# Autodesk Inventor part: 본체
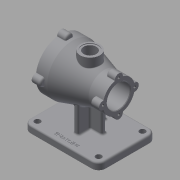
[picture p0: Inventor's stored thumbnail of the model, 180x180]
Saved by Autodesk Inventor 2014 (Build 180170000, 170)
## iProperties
Created: 2020-12
Part Number: 본체
Material: Generic
Document SubType Name: Modeling
Designer: kh
Density: 1 g/cm^3
Appearance: Default
Author: kh
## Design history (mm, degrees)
sketch "스케치1"
  geometry: L1 (-65, -50)-(65, -50); L2 (65, -50)-(65, 50); L3 (65, 50)-(-65, 50); L4 (-65, 50)-(-65, -50); L5 (-65, -50)-(65, 50); L6 (65, -50)-(-65, 50); 1 further point
  constraints: 12 end point, 2 midpoint, 2 parallel, 1 horizontal, 1 perpendicular
  dimensions: "d0" = 130 distance of L1.start L1.end; "d1" = 100 distance of L1.end L2.end
extrude "돌출1" new body sketch "스케치1" distance "d2" = 12; taper "d3" = 0 deg
fillet "모깎기1" dims "d4" = 12
sketch "스케치2"
  geometry: 1 further point
sketch "스케치3"
  geometry: 1 further point
sketch "스케치4"
  geometry: L1 (-65, 38)-(-65, -38) reference; L2 (-53, -50)-(53, -50) reference; L3 (65, -38)-(65, 38) reference; L4 (53, 50)-(-53, 50) reference; C1 r 5 at (-53, 38); C2 r 5 at (53, 38); C3 r 5 at (53, -38); C4 r 5 at (-53, -38); A1 r 12 centre (-53, 38) between (-53, 50) and (-65, 38) reference; A2 r 12 centre (-53, -38) between (-65, -38) and (-53, -50) reference; A3 r 12 centre (53, -38) between (53, -50) and (65, -38) reference; A4 r 12 centre (53, 38) between (65, 38) and (53, 50) reference; 1 further point
  constraints: 4 centre point, 4 coincident
  dimensions: "d5" = 10 diameter of C1; "d6" = 10 diameter of C2; "d7" = 10 diameter of C4; "d8" = 10 diameter of C3
extrude "돌출2" cut sketch "스케치4" distance "d9" = 12; taper "d10" = 0 deg
sketch "스케치5"
  geometry: 1 further point
node "작업 평면1"
sketch "스케치6"
  geometry: L1 (0, 0)-(0, 82); C1 r 44 at (0, 82)
  constraints: 2 end point, 1 centre point, 1 coincident, 1 vertical
  dimensions: "d19" = 82 distance of L1.start L1.end; "d20" = 88 diameter of C1
extrude "돌출3" join sketch "스케치6" distance "d21" = 20; taper "d22" = 0 deg
node "작업 평면2"
sketch "스케치7"
  geometry: L1 (0, 0)-(0, 82); C1 r 27.5 at (0, 82)
  constraints: 2 end point, 1 centre point, 1 coincident, 1 vertical
  dimensions: "d24" = 82 distance of L1.start L1.end; "d25" = 55 diameter of C1
extrude "돌출4" join sketch "스케치7" distance "d26" = 25; taper "d27" = 0 deg
feature "로프트1" dims "d28" = 0, "d29" = 90 deg, "d30" = 0, "d31" = 90 deg
  node "모서리1"
  node "모서리2"
sketch "스케치8"
  geometry: C1 r 7 at (44, 0); C2 r 7 at (0, -44); C3 r 7 at (-44, 0); C4 r 7 at (0, 44); A1 r 44 centre (0, 0) between (44, 0) and (0, -44) reference; 1 further point
  constraints: 4 centre point, 4 point on circle
  dimensions: "d32" = 14 diameter of C1; "d33" = 14 diameter of C2; "d34" = 14 diameter of C3; "d35" = 14 diameter of C4
extrude "돌출5" join sketch "스케치8" distance "d36" = 15; taper "d37" = 0 deg
sketch "스케치9"
  geometry: C1 r 7 at (-27.5, 0); C2 r 7 at (0, 27.5); C3 r 7 at (27.5, 0); C4 r 7 at (0, -27.5); A1 r 27.5 centre (0, 0) between (-27.5, 0) and (0, 27.5) reference; 1 further point
  constraints: 4 centre point, 4 point on circle
  dimensions: "d38" = 14 diameter of C1; "d39" = 14 diameter of C2; "d40" = 14 diameter of C3; "d41" = 14 diameter of C4
extrude "돌출6" join sketch "스케치9" distance "d42" = 15; taper "d43" = 0 deg
fillet "모깎기2" dims "d44" = 1
fillet "모깎기3" dims "d45" = 3
fillet "모깎기4" dims "d46" = 1
fillet "모깎기5" dims "d47" = 3
fillet "모깎기6" dims "d48" = 3
sketch "스케치10"
  geometry: A1 r 44 centre (82, 0) between (89.817, -43.3) and (125.3, -7.817) reference; A2 r 44 centre (82, 0) between (125.3, 7.817) and (89.817, 43.3) reference; A3 r 7 centre (126, 0) between (126.249, -6.996) and (126.249, 6.996) reference; A4 r 7 centre (82, -44) between (75.004, -44.249) and (88.996, -44.249) reference; A5 r 7 centre (82, 44) between (88.996, 44.249) and (75.004, 44.249) reference; A6 r 7 centre (38, 0) between (37.751, 6.996) and (37.751, -6.996) reference; 5 further points
  constraints: 4 coincident
hole "구멍1" sketch "스케치10" at (126, 0), (82, -44), (38, 0), (82, 44) diameter "d49" = 4.134; stored, may be unused: countersink angle "d53" = 90 deg, drill point angle "d55" = 118 deg; dims "d50" = 9, "d51" = 4, "d52" = 2, "d54" = 11
sketch "스케치11"
  geometry: A1 r 7 centre (-109.5, 0) between (-109.373, 6.999) and (-109.373, -6.999) reference; A2 r 7 centre (-82, 27.5) between (-75.001, 27.373) and (-88.999, 27.373) reference; A3 r 7 centre (-54.5, 0) between (-54.627, -6.999) and (-54.627, 6.999) reference; A4 r 7 centre (-82, -27.5) between (-88.999, -27.373) and (-75.001, -27.373) reference; 5 further points
  constraints: 4 coincident
hole "구멍2" sketch "스케치11" at (-109.5, 0), (-82, 27.5), (-54.5, 0), (-82, -27.5) diameter "d56" = 4.134; stored, may be unused: countersink angle "d60" = 90 deg, drill point angle "d62" = 118 deg; dims "d57" = 9, "d58" = 4, "d59" = 2, "d61" = 11
node "작업 평면4"
sketch "스케치12"
  geometry: C1 r 17 at (0, 0); 1 further point
  constraints: 1 centre point, 1 coincident
  dimensions: "d65" = 34 diameter of C1
extrude "돌출7" join sketch "스케치12" stored distance "d66" = 15; taper "d67" = 0 deg
hole "구멍3" diameter "d70" = 64; stored, may be unused: countersink angle "d74" = 90 deg, drill point angle "d76" = 0 deg; dims "d68" = 10, "d69" = 10, "d71" = 9, "d72" = 4, "d73" = 2, "d75" = 23
hole "구멍4" diameter "d79" = 52; stored, may be unused: countersink angle "d83" = 90 deg, drill point angle "d85" = 0 deg; dims "d77" = 10, "d78" = 10, "d80" = 9, "d81" = 4, "d82" = 2, "d84" = 47
hole "구멍5" diameter "d88" = 40; stored, may be unused: countersink angle "d92" = 90 deg, drill point angle "d94" = 0 deg; dims "d86" = 10, "d87" = 10, "d89" = 9, "d90" = 4, "d91" = 2, "d93" = 30
sketch "스케치13"
  geometry: C1 r 14 at (0, 0); 1 further point
  constraints: 1 centre point, 1 coincident
  dimensions: "d95" = 28 diameter of C1
extrude "돌출8" cut sketch "스케치13" distance "d96" = 1; taper "d97" = 0 deg
sketch "스케치14"
  geometry: C1 r 11 at (0, 0); 1 further point
  constraints: 1 centre point, 1 coincident
  dimensions: "d98" = 22 diameter of C1
extrude "돌출9" cut sketch "스케치14" stored distance "d99" = 10; taper "d100" = 0 deg
sketch "스케치15"
  geometry: L1 (53, 12)-(-53, 12) reference; L2 (24, 12)-(24, 49.92); L3 (-24, 12)-(-24, 49.92); L4 (24, 49.92)-(24, 55); L5 (24, 55)-(-24, 55); L6 (-24, 55)-(-24, 49.92); L7 (24, 12)-(-24, 12); 1 further point
  constraints: 12 end point, 2 parallel, 2 perpendicular, 1 collinear, 1 point on line
extrude "돌출10" join sketch "스케치15" stored distance "d103" = 8; taper "d104" = 0 deg
sketch "스케치16"
  geometry: L1 (-25, 12)-(-25, 57); L2 (25, 12)-(25, 57); L3 (-25, 12)-(25, 12); L4 (-25, 57)-(-25, 65); L5 (-25, 65)-(25, 65); L6 (25, 65)-(25, 57); 5 further points
  constraints: 12 end point, 2 perpendicular, 1 parallel
extrude "돌출11" join sketch "스케치16" stored distance "d106" = 8; taper "d107" = 0 deg
hole "구멍6" diameter "d110" = 52; stored, may be unused: countersink angle "d114" = 90 deg, drill point angle "d116" = 0 deg; dims "d108" = 10, "d109" = 10, "d111" = 6, "d112" = 4, "d113" = 2, "d115" = 47
fillet "모깎기8" dims "d117" = 3
fillet "모깎기9" dims "d118" = 3
fillet "모깎기10" dims "d119" = 1
fillet "모깎기11" dims "d120" = 1
fillet "모깎기12" dims "d121" = 3
chamfer "모따기1" distance "d122" = 1; stored, may be unused: second distance "d123" = 2, angle "d124" = 45 deg
sketch "스케치17"
  geometry: 2 further points
  constraints: 1 other
feature "엠보싱1" sketch "스케치17" dims "d127" = 0.5, "d128" = 0
node "솔리드1"
